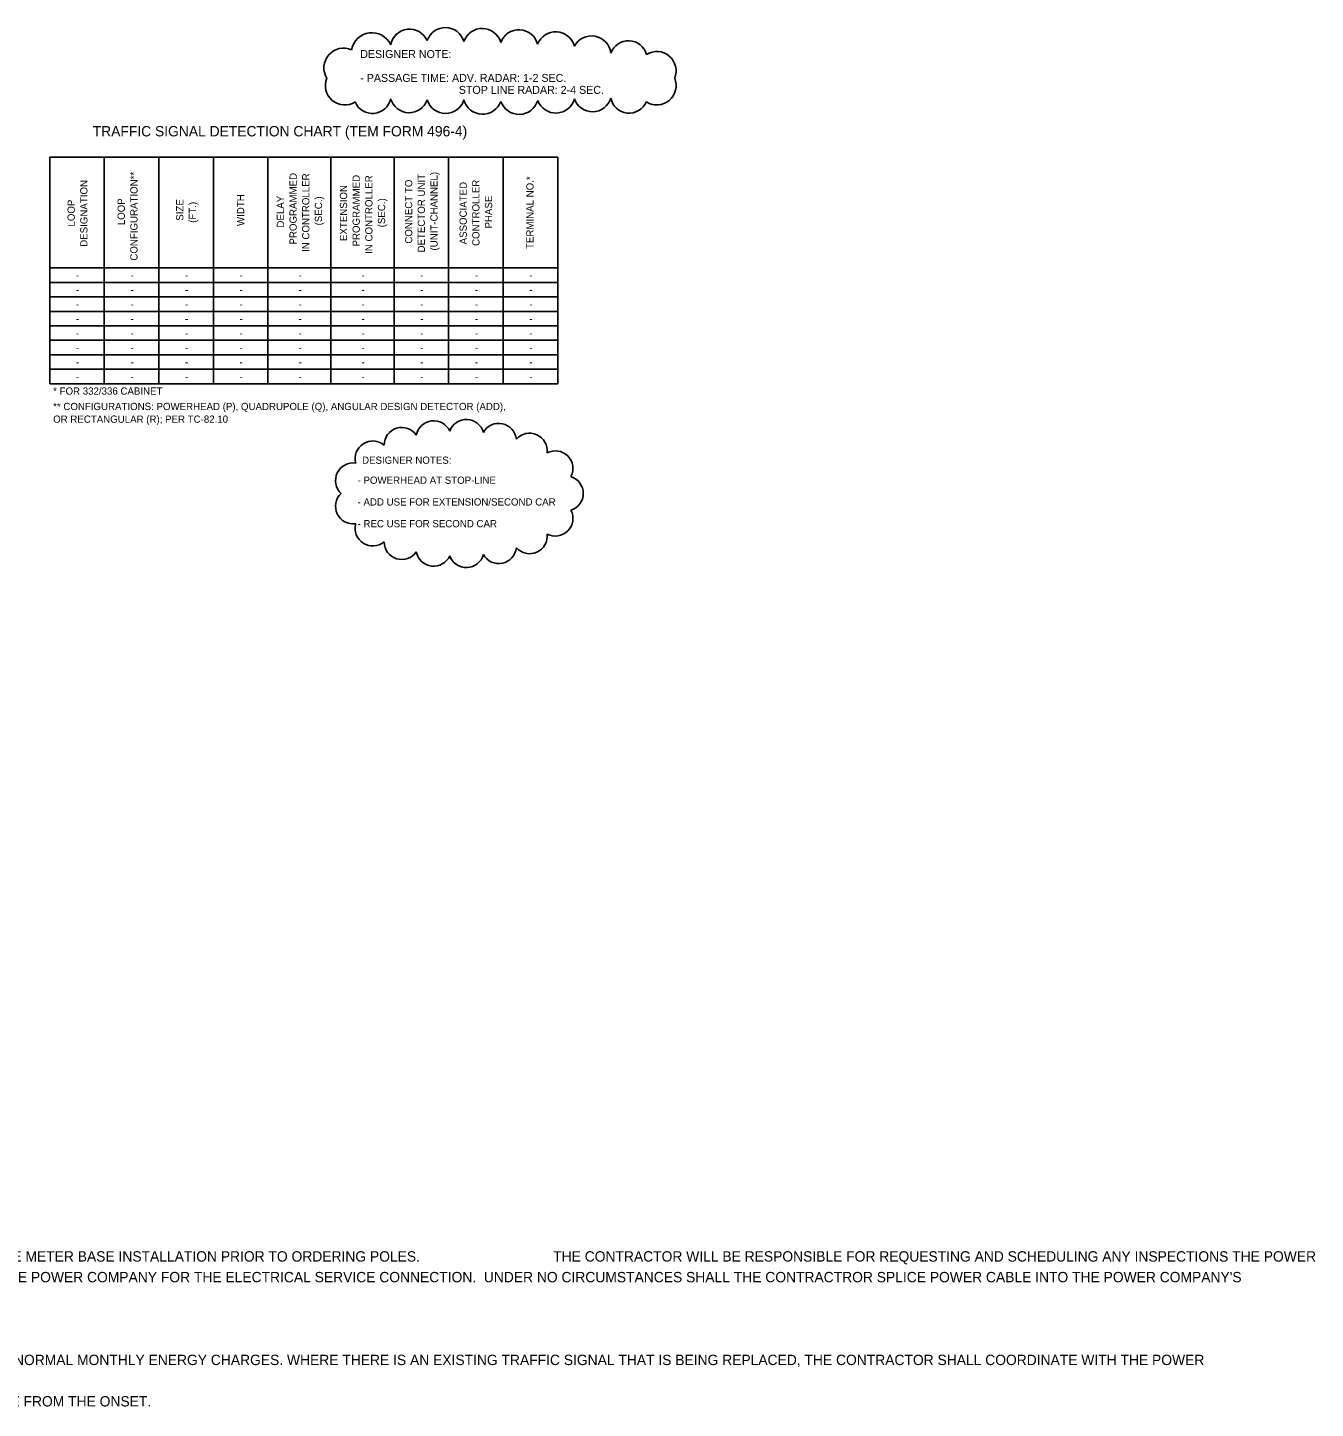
# Model space of a CAD drawing. Extents: x 22.8 to 118.4, y -49.9 to 44.8.
# Drawn here: x 93.52 to 118.41, y 2.76 to 29.44 of the extents above; entities that cross this region are included whole.
import ezdxf

# ---------------------------------------------------------------- set-up
doc = ezdxf.new("R2010")
doc.units = 0
for name, color, linetype in [('SC_Scratch1', 7, 'Continuous'), ('SH_Text', 7, 'Continuous'), ('ST_Text', 7, 'Continuous')]:
    doc.layers.add(name, color=color, linetype=linetype)

msp = doc.modelspace()

# ---------------------------------------------------------------- linework, layer by layer
at = {"layer": 'SC_Scratch1'}
for centre, radius, start, end in [((100.903, 29.043), 0.372, 24.0545, 169.0545), ((101.594, 29.072), 0.373, 15.7944, 160.7944), ((102.307, 29.054), 0.374, 16.3895, 161.3895), ((103.016, 29.028), 0.374, 14.4831, 159.4831), ((103.728, 28.991), 0.373, 14.5779, 159.5779), ((100.175, 28.945), 0.4, 24.833, 169.833), ((104.42, 28.908), 0.376, 6.8087, 151.8087), ((105.132, 28.829), 0.361, 15.0309, 160.0309), ((99.63, 28.665), 0.382, 66.5811, 211.5811), ((105.681, 28.608), 0.374, 337.5685, 122.5685), ((99.65, 28.323), 0.374, 157.5627, 302.5627), ((105.681, 28.323), 0.374, 237.4315, 22.4315), ((100.185, 28.147), 0.362, 202.6672, 347.6672), ((100.894, 28.169), 0.37, 195.5342, 340.5342), ((101.598, 28.158), 0.372, 197.5, 342.5), ((102.313, 28.145), 0.374, 195.3608, 340.3608), ((103.019, 28.141), 0.374, 199.0296, 344.0296), ((103.729, 28.166), 0.373, 200.0602, 345.0602), ((104.439, 28.187), 0.369, 198.4833, 343.4833), ((105.148, 28.153), 0.362, 191.3271, 336.3271), ((100.752, 21.376), 0.341, 34.7029, 179.7029), ((101.368, 21.507), 0.341, 24.2813, 169.2813), ((102, 21.532), 0.341, 15.2835, 160.2835), ((102.627, 21.456), 0.341, 5.8475, 150.8475), ((100.192, 21.116), 0.341, 50.0977, 195.0977), ((103.223, 21.265), 0.341, 353.6423, 138.6423), ((103.719, 20.925), 0.341, 332.4647, 117.4647), ((99.813, 20.69), 0.341, 81.6837, 226.6837), ((103.919, 20.442), 0.341, 287.5, 72.5), ((99.813, 20.194), 0.341, 133.3163, 278.3163), ((103.719, 19.959), 0.341, 242.5353, 27.5353), ((100.192, 19.767), 0.341, 164.9023, 309.9023), ((100.752, 19.507), 0.341, 180.2971, 325.2971), ((103.223, 19.618), 0.341, 221.3577, 6.3577), ((101.368, 19.376), 0.341, 190.7187, 335.7187), ((102, 19.351), 0.341, 199.7165, 344.7165), ((102.627, 19.427), 0.341, 209.1525, 354.1525)]:
    msp.add_arc(centre, radius, start, end, dxfattribs=at)
at = {"layer": 'ST_Text'}
for p, q in [((93.949, 26.942), (103.765, 26.942)), ((93.949, 26.942), (93.949, 22.561)), ((95.003, 26.942), (95.003, 22.561)), ((96.057, 26.942), (96.057, 22.561)), ((97.111, 26.942), (97.111, 22.561)), ((98.165, 26.942), (98.165, 22.561)), ((99.384, 26.942), (99.384, 22.561)), ((100.603, 26.942), (100.603, 22.561)), ((101.657, 26.942), (101.657, 22.561)), ((102.711, 26.942), (102.711, 22.561)), ((103.765, 26.942), (103.765, 22.561)), ((93.949, 24.801), (103.765, 24.801)), ((93.949, 24.521), (103.765, 24.521)), ((93.949, 24.241), (103.765, 24.241)), ((93.949, 23.961), (103.765, 23.961)), ((93.949, 23.681), (103.765, 23.681)), ((93.949, 23.401), (103.765, 23.401)), ((93.949, 23.121), (103.765, 23.121)), ((93.949, 22.841), (103.765, 22.841)), ((93.949, 22.561), (103.765, 22.561))]:
    msp.add_line(p, q, dxfattribs=at)

# ---------------------------------------------------------------- texts
at = {"layer": 'SC_Scratch1'}
for s, height, p in [('DESIGNER NOTE:', 0.154, (99.95, 28.857)), ('- PASSAGE TIME: ADV. RADAR: 1-2 SEC.', 0.154, (99.95, 28.395)), (' STOP LINE RADAR: 2-4 SEC.', 0.154, (101.798, 28.164)), ('DESIGNER NOTES:', 0.14, (99.985, 21.015)), ('- POWERHEAD AT STOP-LINE', 0.14, (99.898, 20.628)), ('- ADD USE FOR EXTENSION/SECOND CAR', 0.14, (99.898, 20.208)), ('- REC USE FOR SECOND CAR', 0.14, (99.898, 19.788))]:
    msp.add_text(s, height=height, dxfattribs=at).set_placement(p)
at = {"layer": 'SH_Text'}
for s, p in [('TRAFFIC SIGNAL DETECTION CHART (TEM FORM 496-4)', (94.78, 27.342)), ('THE CONTRACTOR SHALL CONTACT THE METER SECTION OF <INSERT POWER COMPANY NAME> FOR INFORMATION REGARDING THE METER BASE INSTALLATION PRIOR TO ORDERING POLES. ', (75.679, 5.598)), ('THE CONTRACTOR WILL BE RESPONSIBLE FOR REQUESTING AND SCHEDULING ANY INSPECTIONS THE POWER ', (103.679, 5.598)), ("THE CONTRACTOR SHALL BE RESPONSIBLE TO CONTACT THE POWER COMPANY FOR THE ELECTRICAL SERVICE CONNECTION.  UNDER NO CIRCUMSTANCES SHALL THE CONTRACTROR SPLICE POWER CABLE INTO THE POWER COMPANY'S ", (85.279, 5.198)), ('CONTRACTOR IS RESPONSIBLE FOR OBTAINING ANY NECESSARY PERMITS AND THE PAYING OF ALL FEES WITH THE EXCEPTION OF NORMAL MONTHLY ENERGY CHARGES. WHERE THERE IS AN EXISTING TRAFFIC SIGNAL THAT IS BEING REPLACED, THE CONTRACTOR SHALL COORDINATE WITH THE POWER ', (75.679, 3.598)), ("ACCOUNT. WHERE A NEW SIGNAL IS BEING INSTALLED, THE CONTRACTOR SHALL ESTABLISH THE ACCOUNT IN THE DISTRICT'S NAME FROM THE ONSET.", (75.679, 2.798))]:
    msp.add_text(s, height=0.2, dxfattribs=at).set_placement(p)
at = {"layer": 'ST_Text'}
for s, p in [('DESIGNATION', (94.678, 25.209)), ('CONFIGURATION**', (95.646, 24.941)), ('PROGRAMMED', (98.722, 25.253)), ('IN CONTROLLER', (98.967, 25.109)), ('PROGRAMMED', (99.941, 25.215)), ('IN CONTROLLER ', (100.186, 25.072)), ('CONNECT TO ', (100.955, 25.269)), ('DETECTOR UNIT ', (101.2, 25.098)), ('(UNIT-CHANNEL)', (101.445, 25.137)), ('ASSOCIATED ', (102.009, 25.256)), ('CONTROLLER', (102.254, 25.225)), ('TERMINAL NO.*', (103.299, 25.166)), ('WIDTH', (97.708, 25.61)), ('DELAY ', (98.477, 25.58)), ('(SEC.)', (99.212, 25.622)), ('EXTENSION ', (99.696, 25.32)), ('PHASE', (102.499, 25.562)), ('LOOP', (94.433, 25.6)), ('LOOP', (95.401, 25.626)), ('SIZE', (96.532, 25.713)), ('(FT.)', (96.777, 25.672)), ('(SEC.)', (100.431, 25.585))]:
    msp.add_text(s, height=0.14, rotation=90, dxfattribs=at).set_placement(p)
for s, p in [('-', (94.456, 24.591)), ('-', (95.51, 24.591)), ('-', (96.564, 24.591)), ('-', (97.618, 24.591)), ('-', (98.755, 24.591)), ('-', (99.974, 24.591)), ('-', (101.11, 24.591)), ('-', (102.164, 24.591)), ('-', (103.218, 24.591)), ('-', (94.456, 24.311)), ('-', (95.51, 24.311)), ('-', (96.564, 24.311)), ('-', (97.618, 24.311)), ('-', (98.755, 24.311)), ('-', (99.974, 24.311)), ('-', (101.11, 24.311)), ('-', (102.164, 24.311)), ('-', (103.218, 24.311)), ('-', (94.456, 24.031)), ('-', (95.51, 24.031)), ('-', (96.564, 24.031)), ('-', (97.618, 24.031)), ('-', (98.755, 24.031)), ('-', (99.974, 24.031)), ('-', (101.11, 24.031)), ('-', (102.164, 24.031)), ('-', (103.218, 24.031)), ('-', (94.456, 23.751)), ('-', (95.51, 23.751)), ('-', (96.564, 23.751)), ('-', (97.618, 23.751)), ('-', (98.755, 23.751)), ('-', (99.974, 23.751)), ('-', (101.11, 23.751)), ('-', (102.164, 23.751)), ('-', (103.218, 23.751)), ('-', (94.456, 23.471)), ('-', (95.51, 23.471)), ('-', (96.564, 23.471)), ('-', (97.618, 23.471)), ('-', (98.755, 23.471)), ('-', (99.974, 23.471)), ('-', (101.11, 23.471)), ('-', (102.164, 23.471)), ('-', (103.218, 23.471)), ('-', (94.456, 23.191)), ('-', (95.51, 23.191)), ('-', (96.564, 23.191)), ('-', (97.618, 23.191)), ('-', (98.755, 23.191)), ('-', (99.974, 23.191)), ('-', (101.11, 23.191)), ('-', (102.164, 23.191)), ('-', (103.218, 23.191)), ('-', (94.456, 22.911)), ('-', (95.51, 22.911)), ('-', (96.564, 22.911)), ('-', (97.618, 22.911)), ('-', (98.755, 22.911)), ('-', (99.974, 22.911)), ('-', (101.11, 22.911)), ('-', (102.164, 22.911)), ('-', (103.218, 22.911)), ('-', (94.456, 22.631)), ('-', (95.51, 22.631)), ('-', (96.564, 22.631)), ('-', (97.618, 22.631)), ('-', (98.755, 22.631)), ('-', (99.974, 22.631)), ('-', (101.11, 22.631)), ('-', (102.164, 22.631)), ('-', (103.218, 22.631)), ('* FOR 332/336 CABINET', (94.015, 22.351)), ('** CONFIGURATIONS: POWERHEAD (P), QUADRUPOLE (Q), ANGULAR DESIGN DETECTOR (ADD), ', (94.015, 22.053)), ('OR RECTANGULAR (R); PER TC-82.10', (94.015, 21.808))]:
    msp.add_text(s, height=0.14, dxfattribs=at).set_placement(p)

doc.saveas('drawing.dxf')
